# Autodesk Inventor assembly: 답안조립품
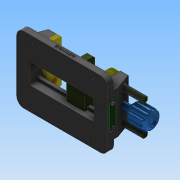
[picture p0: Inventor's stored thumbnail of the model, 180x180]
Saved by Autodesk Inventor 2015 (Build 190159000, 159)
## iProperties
Created: 2018-03
Part Number: 답안조립품
Document SubType Name: Assembly
Designer: SCD-A03
Mass: 1034.81 g
Surface Area: 918.509 cm^2
Volume: 340.421 cm^3
Density: 3.03979 g/cm^3
Author: SCD-A03
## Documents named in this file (10)
- C:\Users\SCD-A03\Desktop\380308V1007\답안조립품.iam
- C:\Users\SCD-A03\Desktop\380308V1007\고정 플레이트.ipt
- C:\Users\SCD-A03\Desktop\380308V1007\바이스본체 A.ipt
- C:\Users\SCD-A03\Desktop\380308V1007\바이스본체 B.ipt
- C:\Users\SCD-A03\Desktop\380308V1007\스퍼기어.ipt
- C:\Users\SCD-A03\Desktop\380308V1007\슬라이딩 부품.ipt
- C:\Users\SCD-A03\Desktop\380308V1007\십자오목머리나사 M3.ipt
- C:\Users\SCD-A03\Desktop\380308V1007\십자오목머리나사 M4.ipt
- C:\Users\SCD-A03\Desktop\380308V1007\지지대.ipt
- C:\Users\SCD-A03\Desktop\380308V1007\핸들.ipt
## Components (3 placed, 2 different names)
1. 고정 플레이트:2
2. 핸들:2 — 각도:1
3. 고정 플레이트:3
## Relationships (1: Angle 1)
- 각도:1 [Angle]: 핸들:2
